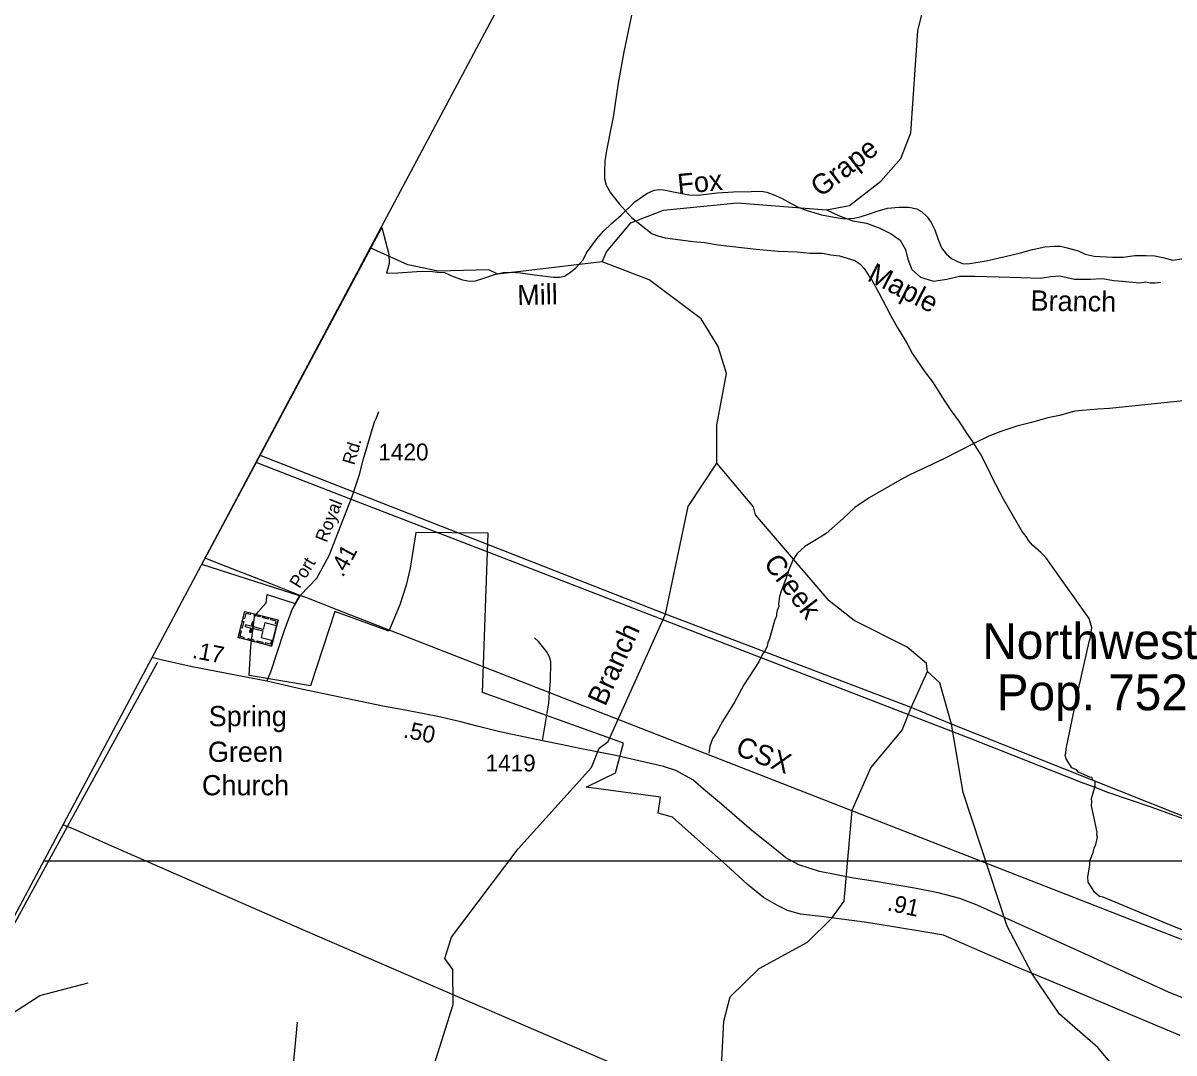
# Model space of a CAD drawing. Extents: x 2225501 to 2309677, y 165449 to 227696.
# Drawn here: x 2244504 to 2253045, y 205240 to 212881 of the extents above; entities that cross this region are included whole.
import ezdxf

# ---------------------------------------------------------------- set-up
doc = ezdxf.new("R2010")
doc.units = 0
for name, color, linetype in [('Black Area Fill Shapes', 7, 'Continuous'), ('E_RDY_CMT_EOP', 7, 'Continuous'), ('MARK ENDS WORD SYMBOL CELL', 7, 'Continuous'), ('Old_Level_3', 7, 'Continuous'), ('Old_Level_33', 7, 'Continuous'), ('Old_Level_41', 7, 'Continuous'), ('Old_Level_51', 7, 'Continuous'), ('P_HYD_Drop_Inlet_Box_Type_A_48_Dia-Bottom_CELL', 7, 'Continuous'), ('P_HYD_Endwall_838_01_48_Dia_Single-Top_CELL', 7, 'Continuous'), ('P_HYD_Endwall_838_01_48_Dia_Single_CELL', 7, 'Continuous'), ('P_HYD_Pipe_Flowable_Fill', 7, 'Continuous'), ('P_HYD_RipRap_Pad_876_02_36in_Outlet_With_Ditch-Top_CELL', 7, 'Continuous'), ('P_HYD_Table_Inlet_Data_CELL', 7, 'Continuous'), ('P_HYD_Typical_Terminator_CELL', 7, 'Continuous'), ('P_RDY_Dimension_Text', 7, 'Continuous'), ('Prop Support', 7, 'Continuous'), ('Scratch_Level_1', 7, 'Continuous'), ('Typical Terminator CELL', 7, 'Continuous')]:
    doc.layers.add(name, color=color, linetype=linetype)

msp = doc.modelspace()

# ---------------------------------------------------------------- linework, layer by layer
at = {"layer": 'Black Area Fill Shapes'}
for p, q in [((2246231.2, 209621.7), (2246301.9, 209594.4)), ((2246301.9, 209594.4), (2246976.2, 209333.8)), ((2246976.2, 209333.8), (2247535.5, 209117.7)), ((2247535.5, 209117.7), (2247965.4, 208951.5)), ((2247965.4, 208951.5), (2249979.6, 208173.1)), ((2244800.4, 206935.8), (2244835, 206920.6)), ((2244835, 206920.6), (2244873.1, 206903.9))]:
    msp.add_line(p, q, dxfattribs=at)
for points in [[(2249979.6, 208173.1), (2251542.5, 207569.2), (2252356.8, 207248), (2252457.2, 207210.6)], [(2252457.2, 207210.6), (2252551.3, 207175.6), (2252873.9, 207066.3), (2253228.9, 206937.2), (2253551.9, 206807.8), (2253690.3, 206744.2)], [(2244873.1, 206903.9), (2245139.4, 206787.1), (2246595.9, 206147.3), (2247912.2, 205580.4), (2249458.9, 204911.2), (2251132.3, 204181.1), (2252660.9, 203525.9), (2253800.5, 203037.4), (2255064.4, 202491.9), (2255394, 202351.2)]]:
    msp.add_lwpolyline(points, dxfattribs=at)
at = {"layer": 'Old_Level_3'}
for p, q in [((2244851.7, 206951.1), (2245504.3, 208141.7)), ((2248359.8, 207555.2), (2248394, 207764.2)), ((2244835, 206920.6), (2244851.7, 206951.1)), ((2243753, 204946.6), (2244835, 206920.6)), ((2246537.5, 205467.2), (2246362.6, 203636.4))]:
    msp.add_line(p, q, dxfattribs=at)
for points in [[(2249152.6, 213344.2), (2249130.4, 213297), (2249097.8, 213217.6), (2249060.4, 213133.6), (2249041.8, 213044.9), (2249004.4, 212867.5), (2248962.5, 212666.8), (2248920.5, 212433.4), (2248883.1, 212181.3), (2248859.8, 212059.9), (2248849.3, 212009.7)], [(2248849.3, 212009.7), (2248836.5, 211947.8), (2248822.5, 211859.1), (2248817.8, 211784.5), (2248817.8, 211723.8), (2248831.8, 211677.1), (2248864.5, 211621.1), (2248929.8, 211537), (2248974.7, 211488.2)], [(2248974.7, 211488.2), (2249020, 211439), (2249172.9, 211316.5), (2249221, 211298.7), (2249269.1, 211287.2), (2249477.1, 211258.9), (2249561.2, 211251.5), (2249661.4, 211234.4), (2249945.5, 211202.6), (2250107.6, 211188.1), (2250249.5, 211183.3), (2250341.7, 211173.9), (2250437.6, 211172.9), (2250497.6, 211161.3), (2250563.6, 211153.8), (2250677.9, 211118.8), (2250714, 211093.1), (2250746.3, 211059.3), (2250784.9, 210997.7), (2250799, 210981.9), (2250855.8, 210878.4), (2250941.1, 210712.9), (2250991.8, 210623.6), (2251060.7, 210510.1), (2251105.3, 210426.4), (2251196.5, 210293.3), (2251253, 210219.8), (2251342.1, 210078.5), (2251392.8, 210002.9), (2251453.3, 209919.6), (2251505.9, 209837.9), (2251560.6, 209760.5)], [(2254032.4, 210180.8), (2253934.3, 210163.7), (2253672.8, 210133.7), (2253496.9, 210118.1), (2252566, 210020.6), (2252480.2, 210015.9), (2252308.3, 210000.5), (2252194.7, 209969.5), (2252108.8, 209951), (2251987.1, 209915.9), (2251879.5, 209891.1), (2251759.7, 209850), (2251670, 209815.4), (2251560.6, 209760.5)], [(2251560.6, 209760.5), (2251337.7, 209648.7), (2251078.8, 209526.5), (2250993.1, 209480), (2250782.1, 209358.4), (2250676.8, 209287.4), (2250589.6, 209204.7), (2250464.5, 209093.8), (2250392.8, 209049.2), (2250305.4, 208996.5), (2250247.8, 208946.1), (2250216.3, 208895.9), (2250175.1, 208793.5), (2250167.3, 208761.5), (2250130.2, 208665.2), (2250118.4, 208627.1), (2250110.8, 208573), (2250113, 208553.2), (2250101.2, 208523), (2250095.5, 208496.9), (2250095.7, 208476.9), (2250081.9, 208454.8), (2250042.9, 208312.6), (2250031.2, 208284.6), (2250025.5, 208258.6), (2250007.7, 208220.3), (2249995.9, 208206.4), (2249979.6, 208173.1)], [(2252457.2, 207210.6), (2252459, 207216.8), (2252460.7, 207252.7), (2252442.7, 207262.7), (2252436.5, 207284.6), (2252420.3, 207286.5), (2252336.1, 207323.8), (2252322, 207339.6), (2252285.9, 207355.3), (2252245.4, 207422.9), (2252237.1, 207448.9), (2252243.1, 207464.9), (2252244.7, 207496.9), (2252337.1, 207937.6), (2252416.3, 208290), (2252424.1, 208312), (2252435.3, 208394.2), (2252414.9, 208464), (2252095.2, 208915.1), (2252056.9, 208952.8), (2251994.6, 209006.2), (2251966.3, 209042.2), (2251948.1, 209071.9), (2251917.8, 209107.7), (2251779.9, 209348.5), (2251694.7, 209509.7), (2251668, 209569.4), (2251609.1, 209685), (2251560.6, 209760.5)], [(2248411.7, 207913.7), (2248418.2, 207997.5), (2248421, 208141.5), (2248412.8, 208173.4), (2248388.5, 208219.1), (2248329.8, 208292.6), (2248299.7, 208318.4)], [(2249979.6, 208173.1), (2249964.4, 208142), (2249853.9, 207971.2), (2249783, 207842.8), (2249694.1, 207700), (2249647, 207611.7), (2249621.1, 207569.4), (2249599.7, 207515.4), (2249592.1, 207463.2)], [(2248394, 207764.2), (2248405.6, 207835.4), (2248411.7, 207913.7)], [(2253426.3, 206025.2), (2253023.1, 206185.8), (2252519.5, 206395.6), (2252491.6, 206401.3), (2252455.3, 206433), (2252408.7, 206506.7), (2252406.5, 206546.6), (2252419.8, 206632.7), (2252421.4, 206664.6), (2252445, 206727), (2252452.6, 206759), (2252464.4, 206787), (2252478, 206841.1), (2252471.9, 206857), (2252475.8, 206879.1), (2252432.2, 207072.5), (2252435.9, 207102.7), (2252433.6, 207128.7), (2252457.2, 207210.6)]]:
    msp.add_lwpolyline(points, dxfattribs=at)
at = {"layer": 'Old_Level_33'}
for points in [[(2246563.9, 208634.9), (2246684.1, 208761.8), (2246776, 208929.2), (2246861.6, 209152.2), (2246945.3, 209368.1), (2247000.8, 209531.6), (2247031, 209648.7), (2247111.8, 209921.4), (2247125.9, 209951.7), (2247144.1, 209998.1)], [(2246314.5, 207997.6), (2246344, 208066.5), (2246442.7, 208369.9), (2246500.7, 208528.6), (2246542.1, 208602.2), (2246563.9, 208634.9)], [(2246314.5, 207997.6), (2245758.1, 208103.3), (2245539, 208153.3), (2245460.1, 208174.2)], [(2253231.8, 205600.6), (2253005.1, 205691.9), (2252565.7, 205890.2), (2252357, 205988.5), (2251584.5, 206336.6), (2251455, 206385.3), (2251294.9, 206428.5), (2251119.5, 206462), (2250831.3, 206512.3), (2250667, 206537.4), (2250413.6, 206586.2), (2250260.4, 206634.9), (2250164.4, 206687.8), (2250107.3, 206733.8), (2250021, 206804.9), (2249912.6, 206890.1), (2249783.8, 207001), (2249686.8, 207084.8), (2249554.3, 207197), (2249473.7, 207266.3), (2249349.2, 207335.4), (2249257, 207364.5), (2248944.3, 207436.2), (2248890.6, 207449.7), (2248774.4, 207470.5), (2248635.6, 207498.6), (2248494, 207528.4), (2248359.8, 207555.2), (2248042.4, 207622.5), (2247875.3, 207664.3), (2247753.6, 207697.4), (2247581.1, 207736.8), (2247338.8, 207782.2), (2247185.5, 207809), (2246569.5, 207939.8), (2246314.5, 207997.6)]]:
    msp.add_lwpolyline(points, dxfattribs=at)
at = {"layer": 'Old_Level_41'}
for points in [[(2245853.3, 208912.2), (2245931.4, 208881.7), (2246341.3, 208721.8), (2246564.3, 208634.7), (2246607, 208618.1)], [(2246607, 208618.1), (2246833.5, 208529.6), (2247935.7, 208099.5), (2248411.7, 207913.7), (2252616.5, 206272.5), (2253402.5, 205966.4)]]:
    msp.add_lwpolyline(points, dxfattribs=at)
at = {"layer": 'Old_Level_51'}
msp.add_lwpolyline([(2252865.1, 222076), (2251536.6, 219580.5), (2249903.4, 216514.9), (2248210.3, 213336.7), (2246230.6, 209620.5), (2243743.1, 204951.1), (2241922.2, 201533.1), (2239717.4, 197394.3), (2237003.1, 192299.2), (2234600.5, 187789.3), (2232018.8, 182943), (2229512.7, 178249.8), (2226733.5, 173036.3), (2226254.7, 172151.4), (2225500.6, 170757.9)], dxfattribs=at)
at = {"layer": 'P_HYD_Endwall_838_01_48_Dia_Single-Top_CELL'}
for points in [[(2246101, 208321.8), (2246150, 208514.7), (2246396.8, 208452), (2246347.8, 208259)], [(2246192.1, 208504.1), (2246189.3, 208493.1), (2246158.1, 208501), (2246148.1, 208461.7), (2246137.3, 208464.5), (2246150.1, 208514.8)], [(2246260.1, 208475), (2246218.1, 208485.7), (2246220.9, 208496.7), (2246262.9, 208486.1)], [(2246119.3, 208393.5), (2246132, 208443.8), (2246143.1, 208441), (2246130.3, 208390.7)], [(2246358.3, 208300.8), (2246386, 208409.5), (2246298.2, 208431.8), (2246285.7, 208382.6), (2246206.7, 208402.7), (2246214.8, 208434.7), (2246204.2, 208437.4), (2246196.1, 208405.4), (2246155.1, 208415.8), (2246152.3, 208404.6), (2246193.2, 208394.1), (2246185, 208362.1), (2246195.7, 208359.4), (2246203.9, 208391.4), (2246282.8, 208371.4), (2246270.6, 208323.1)], [(2246324, 208458.8), (2246282, 208469.4), (2246284.8, 208480.5), (2246326.8, 208469.8)], [(2246388.7, 208419.9), (2246377.5, 208422.7), (2246382.9, 208444), (2246343.8, 208454), (2246346.5, 208464.8), (2246396.8, 208452)], [(2246143, 208311.1), (2246145.8, 208322.1), (2246114.6, 208330), (2246124.6, 208369.3), (2246113.8, 208372.1), (2246101, 208321.8)], [(2246214.8, 208292.8), (2246172.9, 208303.5), (2246175.7, 208314.5), (2246217.6, 208303.8)], [(2246280, 208276.2), (2246238, 208286.9), (2246240.8, 208297.9), (2246282.8, 208287.3)], [(2246355.9, 208291.1), (2246344.7, 208293.9), (2246339.3, 208272.6), (2246300.1, 208282.6), (2246297.4, 208271.8), (2246347.7, 208259)]]:
    msp.add_lwpolyline(points, close=True, dxfattribs=at)
at = {"layer": 'P_HYD_Endwall_838_01_48_Dia_Single_CELL'}
for points in [[(2253090.8, 205369.9), (2252784.2, 205498), (2252381.2, 205668.6), (2251886, 205874.6), (2251607.2, 205996), (2251335.5, 206113.9), (2251204.2, 206136.5), (2250964.8, 206175), (2250748.5, 206209), (2250426.2, 206253), (2250274.5, 206268.7), (2250176.5, 206296.1), (2250102.8, 206335.1), (2249999, 206392.4), (2249876.8, 206492.3), (2249723.5, 206632.4), (2249530.8, 206802.5), (2249323.2, 206989.7), (2249217.2, 207018.2), (2249235.2, 207138.1), (2248683, 207212.6), (2248901.2, 207316.9), (2248959.2, 207537.2), (2247913.5, 207914.5), (2247954.8, 209097), (2247420, 209101.2), (2247377, 208837.2), (2247346.2, 208709.2), (2247299.8, 208565), (2247217.5, 208370), (2246817.8, 208514), (2246637.8, 207963.8), (2246181, 208039.7), (2246195.2, 208255.3), (2246221, 208475.5), (2246249.5, 208511.3), (2246309.2, 208579.4), (2246316, 208640.5), (2246523.5, 208573.3), (2246555.2, 208630.8), (2245831.8, 208863.6), (2247166.8, 211364.4), (2247218, 211166.9), (2247220.5, 211095.5), (2247201.2, 211024), (2247285, 211027.7), (2247426.5, 211037.3), (2247524.2, 211039.9), (2247579.5, 211033.1), (2247631.2, 211028.7), (2247697, 211000), (2247766, 210976), (2247820.2, 210965.8), (2247861.5, 210968.2), (2247923.5, 210988), (2248003, 211014.7), (2248066, 211031.1), (2248126, 211032.4), (2248196, 211028), (2248299.8, 211013.3), (2248360.8, 211004.2), (2248441.2, 210994.1), (2248486, 210995.4), (2248521.8, 211002.4), (2248566.5, 211032.5), (2248606.8, 211064.9), (2248660.5, 211123.8), (2248685.8, 211175.7), (2248727, 211233.5), (2248762.5, 211279.7), (2248812.8, 211336.3), (2248871.2, 211392.9), (2248940.2, 211453.1), (2249043.2, 211553.6), (2249134, 211616.1), (2249186.8, 211641.6), (2249219, 211645.2), (2249256, 211643), (2249331.8, 211628.2), (2249444.8, 211606.6), (2249509, 211603.4), (2249575.8, 211611.6)], [(2249575.8, 211611.6), (2249655, 211621.1), (2249777, 211627.2), (2249908, 211629.9), (2249982.8, 211633.5), (2250024.2, 211625.6), (2250070.2, 211607.3), (2250137.2, 211579.8), (2250198.2, 211544.3), (2250261.5, 211513.3), (2250322.8, 211490.5), (2250429.8, 211458.5), (2250523, 211439.2), (2250600, 211427.9), (2250671.2, 211433.8), (2250717.2, 211442), (2250786.2, 211465.3), (2250842.5, 211485), (2250919.5, 211506), (2251005.8, 211514.3), (2251078.2, 211514.5), (2251137, 211502), (2251170.5, 211481.4), (2251214.2, 211442.3), (2251242, 211400.9), (2251269.8, 211345.7), (2251294, 211275.5), (2251320.8, 211212.1), (2251354.2, 211168.5), (2251394.8, 211134), (2251439.5, 211111.1), (2251483.2, 211095.1), (2251530.5, 211097.5), (2251652.2, 211117.4), (2251791.5, 211147.8), (2251906.2, 211177), (2251994.8, 211200.2), (2252085.8, 211220.1), (2252159.2, 211226.1), (2252201.8, 211225), (2252253.5, 211213.7), (2252334.2, 211189.7), (2252387.2, 211166.8), (2252451.8, 211150.9), (2252588.5, 211144.3), (2252669, 211144.6), (2252755.2, 211155.2), (2252839.2, 211155.4), (2252902.5, 211153.3), (2252963.5, 211142), (2253037.2, 211121.4), (2253136, 211135.5)]]:
    msp.add_lwpolyline(points, dxfattribs=at)
at = {"layer": 'P_HYD_RipRap_Pad_876_02_36in_Outlet_With_Ditch-Top_CELL'}
for points in [[(2253090.8, 205369.9), (2252784.2, 205498), (2252381.2, 205668.6), (2251886, 205874.6), (2251607.2, 205996), (2251335.5, 206113.9), (2251204.2, 206136.5), (2250964.8, 206175), (2250748.5, 206209), (2250426.2, 206253), (2250274.5, 206268.7), (2250176.5, 206296.1), (2250102.8, 206335.1), (2249999, 206392.4), (2249876.8, 206492.3), (2249723.5, 206632.4), (2249530.8, 206802.5), (2249323.2, 206989.7), (2249217.2, 207018.2), (2249235.2, 207138.1), (2248683, 207212.6), (2248901.2, 207316.9), (2248959.2, 207537.2), (2247913.5, 207914.5), (2247954.8, 209097), (2247420, 209101.2), (2247377, 208837.2), (2247346.2, 208709.2), (2247299.8, 208565), (2247217.5, 208370), (2246817.8, 208514), (2246637.8, 207963.8), (2246181, 208039.7), (2246195.2, 208255.3), (2246221, 208475.5), (2246249.5, 208511.3), (2246309.2, 208579.4), (2246316, 208640.5), (2246523.5, 208573.3), (2246555.2, 208630.8), (2245831.8, 208863.6), (2247166.8, 211364.4), (2247218, 211166.9), (2247220.5, 211095.5), (2247201.2, 211024), (2247285, 211027.7), (2247426.5, 211037.3), (2247524.2, 211039.9), (2247579.5, 211033.1), (2247631.2, 211028.7), (2247697, 211000), (2247766, 210976), (2247820.2, 210965.8), (2247861.5, 210968.2), (2247923.5, 210988), (2248003, 211014.7), (2248066, 211031.1), (2248126, 211032.4), (2248196, 211028), (2248299.8, 211013.3), (2248360.8, 211004.2), (2248441.2, 210994.1), (2248486, 210995.4), (2248521.8, 211002.4), (2248566.5, 211032.5), (2248606.8, 211064.9), (2248660.5, 211123.8), (2248685.8, 211175.7), (2248727, 211233.5), (2248762.5, 211279.7), (2248812.8, 211336.3), (2248871.2, 211392.9), (2248940.2, 211453.1), (2249043.2, 211553.6), (2249134, 211616.1), (2249186.8, 211641.6), (2249219, 211645.2), (2249256, 211643), (2249331.8, 211628.2), (2249444.8, 211606.6), (2249509, 211603.4), (2249575.8, 211611.6)], [(2249575.8, 211611.6), (2249655, 211621.1), (2249777, 211627.2), (2249908, 211629.9), (2249982.8, 211633.5), (2250024.2, 211625.6), (2250070.2, 211607.3), (2250137.2, 211579.8), (2250198.2, 211544.3), (2250261.5, 211513.3), (2250322.8, 211490.5), (2250429.8, 211458.5), (2250523, 211439.2), (2250600, 211427.9), (2250671.2, 211433.8), (2250717.2, 211442), (2250786.2, 211465.3), (2250842.5, 211485), (2250919.5, 211506), (2251005.8, 211514.3), (2251078.2, 211514.5), (2251137, 211502), (2251170.5, 211481.4), (2251214.2, 211442.3), (2251242, 211400.9), (2251269.8, 211345.7), (2251294, 211275.5), (2251320.8, 211212.1), (2251354.2, 211168.5), (2251394.8, 211134), (2251439.5, 211111.1), (2251483.2, 211095.1), (2251530.5, 211097.5), (2251652.2, 211117.4), (2251791.5, 211147.8), (2251906.2, 211177), (2251994.8, 211200.2), (2252085.8, 211220.1), (2252159.2, 211226.1), (2252201.8, 211225), (2252253.5, 211213.7), (2252334.2, 211189.7), (2252387.2, 211166.8), (2252451.8, 211150.9), (2252588.5, 211144.3), (2252669, 211144.6), (2252755.2, 211155.2), (2252839.2, 211155.4), (2252902.5, 211153.3), (2252963.5, 211142), (2253037.2, 211121.4), (2253136, 211135.5)]]:
    msp.add_lwpolyline(points, dxfattribs=at)
at = {"layer": 'P_HYD_Typical_Terminator_CELL'}
msp.add_line((2244656.7, 206666.1), (2298327.4, 206666.1), dxfattribs=at)
at = {"layer": 'Prop Support'}
for p, q in [((2249271.7, 208494.2), (2246259.4, 209674.7)), ((2251093.6, 207802.7), (2249271.7, 208494.2)), ((2251093.6, 207802.7), (2251216.6, 208069.3)), ((2251394.6, 207678.7), (2251093.6, 207802.7))]:
    msp.add_line(p, q, dxfattribs=at)
for points in [[(2251394.6, 207678.7), (2251308.7, 207985.5), (2251216.6, 208069.3)], [(2252076.2, 201566), (2251466.5, 201907.6), (2249835.6, 202716.8), (2249793.5, 202776.6), (2249592.6, 202898.7), (2249516.7, 203008.3), (2249473.6, 203130.6), (2249425.7, 203938.4), (2249382.6, 204090.1), (2249397.6, 204296.5), (2249469.5, 204606.7), (2249642.6, 204872.3), (2249682.6, 205042.1), (2249704.5, 205474.6), (2249752.5, 205657.4), (2249967.6, 205866.4), (2250324.6, 206062.8), (2250506.7, 206239.7), (2250596.7, 206365.9), (2250657.6, 207040.4), (2250796.6, 207355.8), (2251027.5, 207633.4), (2251093.6, 207802.7)], [(2252673.7, 205006.7), (2252673.7, 205049.4), (2252479.7, 205279.5), (2252194.7, 205527.8), (2251992.7, 205826.9), (2251806.7, 206181.5), (2251481.7, 207171.9), (2251394.6, 207678.7)], [(2259716.8, 204515.2), (2259332.8, 204653.9), (2258472.8, 204864.2), (2251394.6, 207678.7)], [(2244041, 205510.3), (2244356.6, 205490.4), (2244629.5, 205665.4), (2244987.5, 205760.1)]]:
    msp.add_lwpolyline(points, dxfattribs=at)
at = {"layer": 'Typical Terminator CELL'}
for points in [[(2250466.3, 211495.5), (2250637.5, 211527.9), (2250869.6, 211707.1), (2251018.7, 211874.7), (2251091.7, 212066.9), (2251144.6, 212823.5), (2251369.6, 213744.1), (2251534.6, 214019.7), (2251682.7, 214154.6), (2252073.7, 214255.2), (2252347.7, 214384.3), (2252727.6, 214737.7)], [(2248800.7, 211107.8), (2248833.7, 211182.6), (2249014.5, 211398.8), (2249255.7, 211492.6), (2249804.6, 211547.5), (2250466.3, 211495.5)], [(2250466.3, 211495.5), (2250554.3, 211452.3), (2250662.9, 211413.5), (2250763.4, 211396.6), (2250861.8, 211359.7), (2250946.3, 211316.6), (2251013.2, 211269.2), (2251051.9, 211199.5), (2251068.9, 211129.6), (2251099.9, 211051.8), (2251164.7, 210996.4), (2251261.1, 210965.5), (2251358.9, 210980.7), (2251452.6, 211003.8), (2251566.8, 211003.1), (2251748.9, 210997.2), (2251909, 210993.1), (2252053.4, 210986.8), (2252131.1, 210999.7), (2252199.2, 211004.5), (2252305.6, 210979.7), (2252425.6, 210981.1), (2252511.7, 210986.1), (2252597.8, 210971.1), (2252664, 210965.9), (2252790.4, 210953.3), (2252836.3, 210959.9), (2252868.5, 210954.3), (2252902.3, 210952.6), (2252948.5, 210959.2)], [(2248800.7, 211107.8), (2248026.6, 211017.9), (2247959.5, 211048.8), (2247585.5, 211039.7), (2247359.6, 211086.8), (2247079, 211213.1)], [(2249653.7, 209615.1), (2249651.6, 209897.2), (2249723.6, 210279.6), (2249663.5, 210480.9), (2249536.6, 210686.7), (2249151.5, 210976.3), (2248800.7, 211107.8)], [(2249271.7, 208494.2), (2249440.6, 209294.6), (2249653.7, 209615.1)], [(2251216.6, 208069.3), (2251207.6, 208128.5), (2251064.6, 208249.3), (2250671.6, 208447.3), (2250486.6, 208595.2), (2249940.5, 209232.4), (2249923.5, 209291.7), (2249653.7, 209615.1)], [(2247029.6, 203486.5), (2247695.6, 205599.1), (2247693.6, 205858.3), (2247634.5, 205941.4), (2247683.5, 206097.9), (2248177.5, 206754.1), (2248722.5, 207356.9), (2248779.5, 207500.1), (2248846.6, 207551.3), (2249271.7, 208494.2)]]:
    msp.add_lwpolyline(points, dxfattribs=at)

# ---------------------------------------------------------------- texts
at = {"layer": 'E_RDY_CMT_EOP'}
for s, p in [('1420', (2247141.2, 209635.9)), ('1419', (2247936.4, 207328.6))]:
    msp.add_text(s, height=125, dxfattribs=at).set_placement(p)
at = {"layer": 'MARK ENDS WORD SYMBOL CELL'}
for s, rotation, p in [('Rd.', 73.61055, (2246962.4, 209596.6)), ('Royal', 68.48559, (2246757.1, 209021.7)), ('Port ', 58.35265, (2246556, 208680.4))]:
    msp.add_text(s, height=95, rotation=rotation, dxfattribs=at).set_placement(p)
at = {"layer": 'P_HYD_Drop_Inlet_Box_Type_A_48_Dia-Bottom_CELL'}
for s, p in [('Northwest', (2251622.3, 208162.2)), ('Pop. 752', (2251729.3, 207782.7))]:
    msp.add_text(s, height=265, dxfattribs=at).set_placement(p)
at = {"layer": 'P_HYD_Pipe_Flowable_Fill'}
msp.add_text('CSX', height=150, rotation=339.21611, dxfattribs=at).set_placement((2249782.1, 207454.5))
at = {"layer": 'P_HYD_Table_Inlet_Data_CELL'}
for s, p in [('Spring', (2245881.7, 207664)), ('Green', (2245875.9, 207399.4)), ('Church', (2245831.5, 207151.3))]:
    msp.add_text(s, height=150, dxfattribs=at).set_placement(p)
at = {"layer": 'P_RDY_Dimension_Text'}
for s, rotation, p in [('.41', 61.24112, (2246877.2, 208762.9)), ('.17', 349.23778, (2245754.2, 208171.4)), ('.50', 348.41374, (2247320.8, 207582)), ('.91', 347.65792, (2250911.7, 206299))]:
    msp.add_text(s, height=125, rotation=rotation, dxfattribs=at).set_placement(p)
at = {"layer": 'Scratch_Level_1'}
for s, rotation, p in [('Grape', 37.66713, (2250422, 211583.2)), ('Fox', 5.70898, (2249367.4, 211609.9)), ('Maple', 332.92025, (2250760.1, 210973.7)), ('Mill', 1.39957, (2248173.1, 210787.4)), ('Branch', 359.09111, (2251979.9, 210747.9)), ('Creek', 307.27282, (2249993.3, 208870.9)), ('Branch', 65.73331, (2248824.3, 207805.4))]:
    msp.add_text(s, height=150, rotation=rotation, dxfattribs=at).set_placement(p)

doc.saveas('drawing.dxf')
